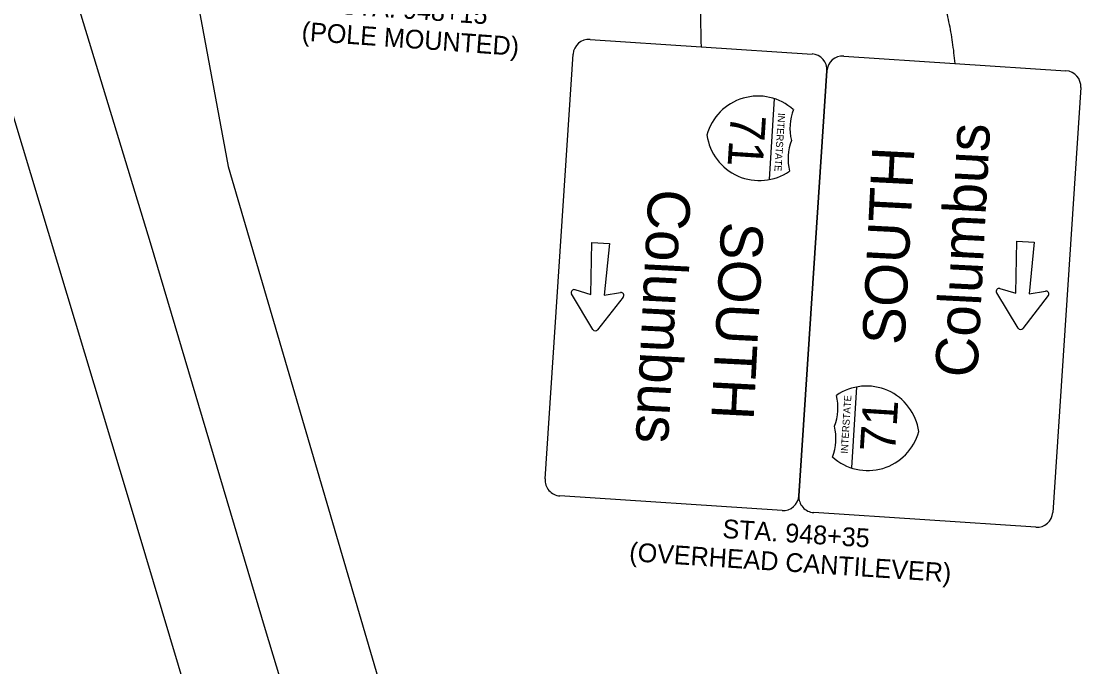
# Model space of a CAD drawing. Extents: x 1847379 to 1850904, y 217032 to 220169.
# Drawn here: x 1848911.4 to 1849052.4, y 218651.2 to 218737.1 of the extents above; entities that cross this region are included whole.
import ezdxf

# ---------------------------------------------------------------- set-up
doc = ezdxf.new("R2010")
doc.units = 0
for name, color, linetype in [('BR_P_Gen_Approach_Slab_Hidden', 7, 'Continuous'), ('PM_X_Channelizing_Line', 7, 'Continuous'), ('SN_X_Public', 7, 'Continuous'), ('SN_X_Text', 7, 'Continuous')]:
    doc.layers.add(name, color=color, linetype=linetype)

msp = doc.modelspace()

# ---------------------------------------------------------------- linework, layer by layer
at = {"layer": 'BR_P_Gen_Approach_Slab_Hidden'}
for p, q in [((1848928.66, 218773.07), (1848938.92, 218717.78)), ((1848910.26, 218724.65), (1848925.73, 218673.2)), ((1848938.92, 218717.78), (1848966.43, 218623.91)), ((1848925.73, 218673.2), (1848942.21, 218618.05))]:
    msp.add_line(p, q, dxfattribs=at)
at = {"layer": 'PM_X_Channelizing_Line'}
msp.add_lwpolyline([(1848911.49, 218763.7), (1848928.55, 218707.66), (1848943.83, 218656.11), (1848955.22, 218618.44), (1848971.95, 218561.87), (1848985.85, 218514.54), (1849001.62, 218461.72), (1849015.55, 218410.53), (1849029.52, 218359.59)], dxfattribs=at)
at = {"layer": 'SN_X_Public'}
for p, q in [((1849011.56, 218726.84), (1849010.87, 218716.04)), ((1848987.17, 218700.75), (1848987.32, 218707.67)), ((1848987.32, 218707.67), (1848989.65, 218707.52)), ((1848989.65, 218707.52), (1848988.92, 218700.64)), ((1849043.72, 218700.92), (1849043.82, 218707.84)), ((1849043.82, 218707.84), (1849046.15, 218707.71)), ((1849046.15, 218707.71), (1849045.48, 218700.82)), ((1848987.44, 218696.07), (1848984.6, 218700.83)), ((1848985.04, 218701.39), (1848987.17, 218700.75)), ((1848988.92, 218700.64), (1848991.11, 218701)), ((1849044.03, 218696.25), (1849041.16, 218700.98)), ((1849041.59, 218701.54), (1849043.72, 218700.92)), ((1849045.48, 218700.82), (1849047.67, 218701.2)), ((1848991.47, 218700.39), (1848988.05, 218696.04)), ((1849048.03, 218700.59), (1849044.65, 218696.22)), ((1849021.87, 218677.64), (1849022.56, 218688.44))]:
    msp.add_line(p, q, dxfattribs=at)
for points in [[(1848987.06, 218734.72), (1849016.61, 218732.77)], [(1848981.08, 218676.18), (1848984.81, 218732.75)], [(1849020.83, 218732.49), (1849050.38, 218730.54)], [(1849018.58, 218730.52), (1849014.85, 218673.95)], [(1849014.85, 218673.95), (1849018.58, 218730.52)], [(1849052.35, 218728.29), (1849048.62, 218671.73)], [(1849012.6, 218671.98), (1848983.05, 218673.93)], [(1849046.37, 218669.76), (1849016.82, 218671.7)]]:
    msp.add_lwpolyline(points, dxfattribs=at)
for centre, radius, start, end in [((1848986.92, 218732.61), 2.12, 86.2275, 176.2275), ((1849016.47, 218730.66), 2.12, 356.2275, 86.2275), ((1849020.69, 218730.38), 2.12, 86.2275, 176.2275), ((1849050.24, 218728.43), 2.12, 356.2275, 86.2275), ((1849009.4, 218720.14), 7.03, 48.0116, 164.8057), ((1849020.69, 218722.89), 7.03, 159.3517, 193.3335), ((1849009.58, 218722.95), 7.03, 187.8796, 304.6737), ((1849020.43, 218718.79), 7.03, 159.3517, 193.3335), ((1848984.93, 218701.02), 0.38, 73.3664, 210.8397), ((1848991.17, 218700.62), 0.38, 321.8455, 99.3188), ((1849041.48, 218701.18), 0.38, 73.8048, 211.2781), ((1849047.73, 218700.83), 0.38, 322.2839, 99.7572), ((1848987.76, 218696.28), 0.38, 212.249, 320.4363), ((1849044.35, 218696.46), 0.38, 212.6874, 320.8747), ((1849023.84, 218681.52), 7.03, 7.8796, 124.6737), ((1849013, 218685.68), 7.03, 339.3517, 13.3335), ((1849012.74, 218681.58), 7.03, 339.3517, 13.3335), ((1849024.02, 218684.33), 7.03, 228.0116, 344.8057), ((1848983.19, 218676.04), 2.12, 176.2275, 266.2275), ((1849012.74, 218674.09), 2.12, 266.2275, 356.2275), ((1849016.96, 218673.81), 2.12, 176.2275, 266.2275), ((1849046.51, 218671.87), 2.12, 266.2275, 356.2275)]:
    msp.add_arc(centre, radius, start, end, dxfattribs=at)
for points in [[(1848968.65, 218812.08), (1848963.26, 218811.77), (1848959.87, 218808.8), (1848962.37, 218795.34), (1848972.61, 218782.93), (1849002.07, 218764.9), (1849001.83, 218733.74)], [(1848970.64, 218811.94), (1848978.12, 218810.73), (1848991.68, 218800.45), (1849010.03, 218768.73), (1849033.87, 218749.22), (1849035.6, 218731.52)]]:
    msp.add_open_spline(points, degree=2, dxfattribs=at)

# ---------------------------------------------------------------- texts
for s, height, rotation, p in [('INTERSTATE', 0.937, 266.3426, (1849012.08, 218724.94)), ('71', 4.688, 266.3426, (1849005.8, 218724.83)), ('Columbus', 5.625, 87.0754, (1849038.57, 218689.6)), ('SOUTH', 5.625, 87.0754, (1849028.89, 218693.95)), ('Columbus', 5.625, 267.0754, (1848994.86, 218714.87)), ('SOUTH', 5.625, 267.0754, (1849004.54, 218710.52)), ('INTERSTATE', 0.937, 86.3426, (1849021.34, 218679.53)), ('71', 4.688, 86.3426, (1849027.63, 218679.64)), ('STA. 948+35', 2.5, 356.2275, (1849004.62, 218668.33)), ('(OVERHEAD CANTILEVER)', 2.5, 356.2275, (1848992.22, 218665.24))]:
    msp.add_text(s, height=height, rotation=rotation, dxfattribs=at).set_placement(p)
at = {"layer": 'SN_X_Text'}
for s, p in [('STA. 948+15', (1848953.79, 218738.11)), ('(POLE MOUNTED)', (1848948.63, 218734.57))]:
    msp.add_text(s, height=2.5, rotation=355.9402, dxfattribs=at).set_placement(p)

doc.saveas('drawing.dxf')
